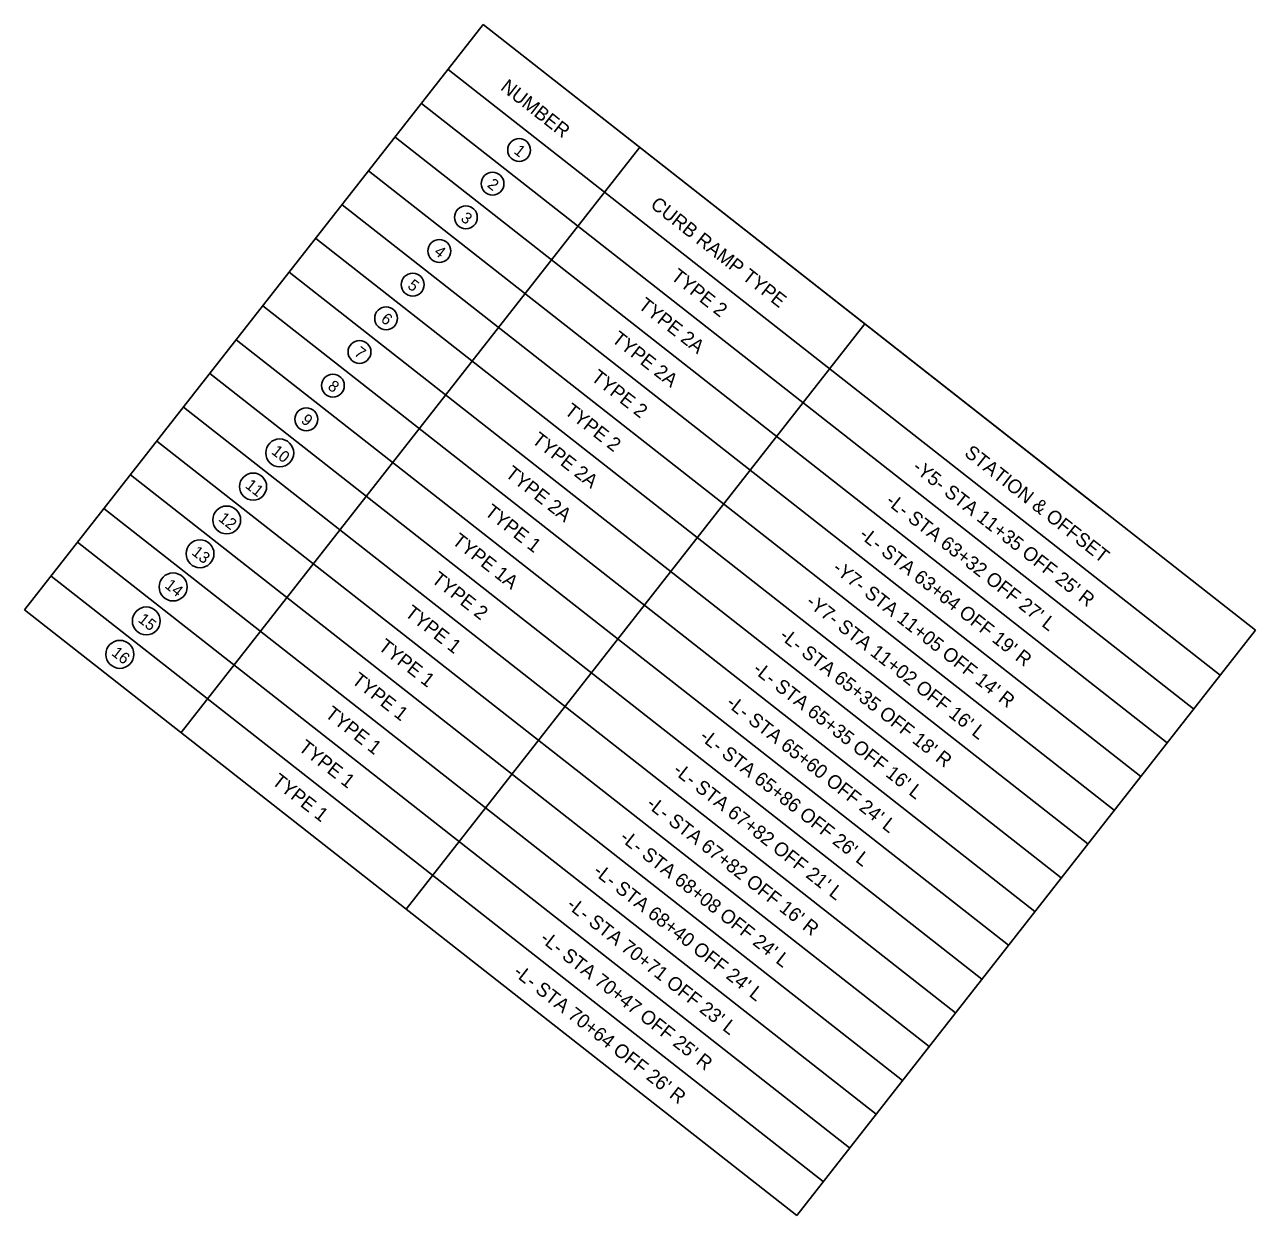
# Model space of a CAD drawing. Extents: x 553958 to 562499, y 493978 to 516388.
# Drawn here: x 561820.4 to 562250.8, y 498066.1 to 498482.4 of the extents above; entities that cross this region are included whole.
import ezdxf

# ---------------------------------------------------------------- set-up
doc = ezdxf.new("R2010")
doc.units = 0
for name, color, linetype in [('Default', 7, 'Continuous'), ('Prop DSN Text', 7, 'Continuous'), ('Prop EOT', 7, 'Continuous')]:
    doc.layers.add(name, color=color, linetype=linetype)

msp = doc.modelspace()

# ---------------------------------------------------------------- linework, layer by layer
at = {"layer": 'Default'}
for p, q in [((561820.38, 498277.79), (561980.8, 498482.39)), ((561980.8, 498482.39), (562196.07, 498313.61)), ((561980.8, 498482.39), (562250.82, 498270.68)), ((561968.46, 498466.65), (562238.48, 498254.94)), ((561959.21, 498454.85), (562229.22, 498243.14)), ((561875.1, 498234.88), (562035.53, 498439.49)), ((561949.95, 498443.05), (562219.96, 498231.33)), ((561940.7, 498431.24), (562210.71, 498219.53)), ((561931.44, 498419.44), (562201.45, 498207.73)), ((561922.19, 498407.63), (562192.2, 498195.92)), ((561912.93, 498395.83), (562182.94, 498184.12)), ((561903.68, 498384.02), (562173.69, 498172.31)), ((561953.79, 498173.18), (562114.22, 498377.78)), ((561894.42, 498372.22), (562164.43, 498160.51)), ((561885.17, 498360.42), (562155.18, 498148.7)), ((561875.91, 498348.61), (562145.92, 498136.9)), ((561866.65, 498336.81), (562136.67, 498125.1)), ((561857.4, 498325), (562127.41, 498113.29)), ((561848.14, 498313.2), (562118.15, 498101.49)), ((561838.89, 498301.4), (562108.9, 498089.68)), ((561829.63, 498289.59), (562099.64, 498077.88)), ((561820.38, 498277.79), (562090.39, 498066.08)), ((562250.82, 498270.68), (562090.39, 498066.08))]:
    msp.add_line(p, q, dxfattribs=at)
at = {"layer": 'Prop DSN Text'}
for centre, radius in [((561993.32, 498438.54), 3.99), ((561984.02, 498426.78), 3.99), ((561974.71, 498415.01), 3.99), ((561965.41, 498403.24), 3.99), ((561956.11, 498391.48), 3.99), ((561946.8, 498379.71), 3.99), ((561937.5, 498367.95), 3.99), ((561928.2, 498356.18), 3.99), ((561918.89, 498344.41), 3.99), ((561909.59, 498332.65), 4.89), ((561900.29, 498320.88), 4.73), ((561891.05, 498309.21), 4.87), ((561881.72, 498297.39), 4.88), ((561872.32, 498285.79), 4.91), ((561862.93, 498273.91), 4.87), ((561853.68, 498262.22), 4.9)]:
    msp.add_circle(centre, radius, dxfattribs=at)

# ---------------------------------------------------------------- texts
at = {"layer": 'Default'}
for s, p in [('NUMBER ', (561986.5, 498459.86)), ('CURB RAMP TYPE', (562038.89, 498418.79)), ('TYPE 2', (562046.08, 498393.66)), ('TYPE 2A', (562034.67, 498383.55)), ('TYPE 2A', (562025.37, 498371.79)), ('TYPE 2', (562018.17, 498358.36)), ('TYPE 2', (562008.86, 498346.59)), ('TYPE 2A', (561997.46, 498336.49)), ('STATION & OFFSET', (562148.71, 498331.96)), ('TYPE 2A', (561988.16, 498324.72)), ("-Y5- STA 11+35 OFF 25' R", (562130.53, 498326.89)), ('TYPE 1', (561980.95, 498311.3)), ("-L- STA 63+32 OFF 27' L", (562121.22, 498315.12)), ('TYPE 1A', (561969.55, 498301.19)), ("-L- STA 63+64 OFF 19' R", (562111.92, 498303.35)), ("-Y7- STA 11+05 OFF 14' R", (562102.61, 498291.59)), ('TYPE 2', (561962.35, 498287.76)), ("-Y7- STA 11+02 OFF 16' L", (562093.31, 498279.82)), ('TYPE 1', (561953.04, 498276)), ('TYPE 1', (561943.74, 498264.23)), ("-L- STA 65+35 OFF 18' R", (562084.01, 498268.05)), ("-L- STA 65+35 OFF 16' L", (562074.7, 498256.29)), ('TYPE 1', (561934.44, 498252.46)), ("-L- STA 65+60 OFF 24' L", (562065.4, 498244.52)), ('TYPE 1', (561925.13, 498240.7)), ('TYPE 1', (561915.83, 498228.93)), ("-L- STA 65+86 OFF 26' L", (562056.1, 498232.76)), ('TYPE 1', (561906.52, 498217.17)), ("-L- STA 67+82 OFF 21' L", (562046.79, 498220.99)), ("-L- STA 67+82 OFF 16' R", (562037.49, 498209.22)), ("-L- STA 68+08 OFF 24' L", (562028.19, 498197.46)), ("-L- STA 68+40 OFF 24' L", (562018.88, 498185.69)), ("-L- STA 70+71 OFF 23' L", (562009.58, 498173.93)), ("-L- STA 70+47 OFF 25' R", (562000.28, 498162.16)), ("-L- STA 70+64 OFF 26' R", (561990.97, 498150.39))]:
    msp.add_text(s, height=4.86, rotation=321.9005, dxfattribs=at).set_placement(p)
at = {"layer": 'Prop EOT'}
for s, p in [('1', (561991.2, 498437.67)), ('2', (561981.9, 498425.9)), ('3', (561972.59, 498414.14)), ('4', (561963.29, 498402.37)), ('5', (561953.99, 498390.6)), ('6', (561944.68, 498378.84)), ('7', (561935.38, 498367.07)), ('8', (561926.08, 498355.31)), ('9', (561916.77, 498343.54)), ('10', (561906.4, 498332.62)), ('11', (561897.26, 498320.73)), ('12', (561887.88, 498309.17)), ('13', (561878.55, 498297.35)), ('14', (561869.11, 498285.78)), ('15', (561859.76, 498273.87)), ('16', (561850.49, 498262.19))]:
    msp.add_text(s, height=4, rotation=321.6667, dxfattribs=at).set_placement(p)

doc.saveas('drawing.dxf')
